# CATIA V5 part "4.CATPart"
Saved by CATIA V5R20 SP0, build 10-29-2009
Part number: 4
Bounding box of the stored display mesh (mm): x -45 to 45, y -60 to 60, z 0 to 20
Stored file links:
  E:\Ehsan\Amoozesh\CATIA\CATIA Course\Advanced\Exercises\DMU Kinematic\11\4.CATPart
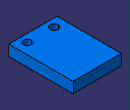
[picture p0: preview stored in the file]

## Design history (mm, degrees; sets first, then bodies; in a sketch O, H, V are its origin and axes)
Body1 (main body)
  Sketch1 on xy-plane, origin (0, 0, 0), H (1, 0, 0), V (0, 1, 0)
    line L1 (45, 60) -> (45, -60)
    line L2 (45, -60) -> (-45, -60)
    line L3 (-45, -60) -> (-45, 60)
    line L4 (-45, 60) -> (45, 60)
    length L4 = 90
    length L1 = 120
    vertical: L1 V, L3 V
    horizontal: L2 H, L4 H
    equidistance: L1 L3 O, L2 L4 O
  Pad1: profile Sketch1, direction (0, 0, 1), length 20
  Sketch2 on end face of Pad1, origin (0, 0, 20), H (1, 0, 0), V (0, 1, 0)
    circle A1 centre (25, -45) radius 7.5
    point P1 (25, -45)
    point P2 (-25, -45)
    circle A2 centre (-25, -45) radius 7.5
    radius A1 = 7.5
    distance P1 P2 = 50
    distance P1 H = 45
    symmetry: A1 A2 V, P1 P2 V
  Pocket1: profile Sketch2, direction (0, 0, -1), through (limit type 6)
